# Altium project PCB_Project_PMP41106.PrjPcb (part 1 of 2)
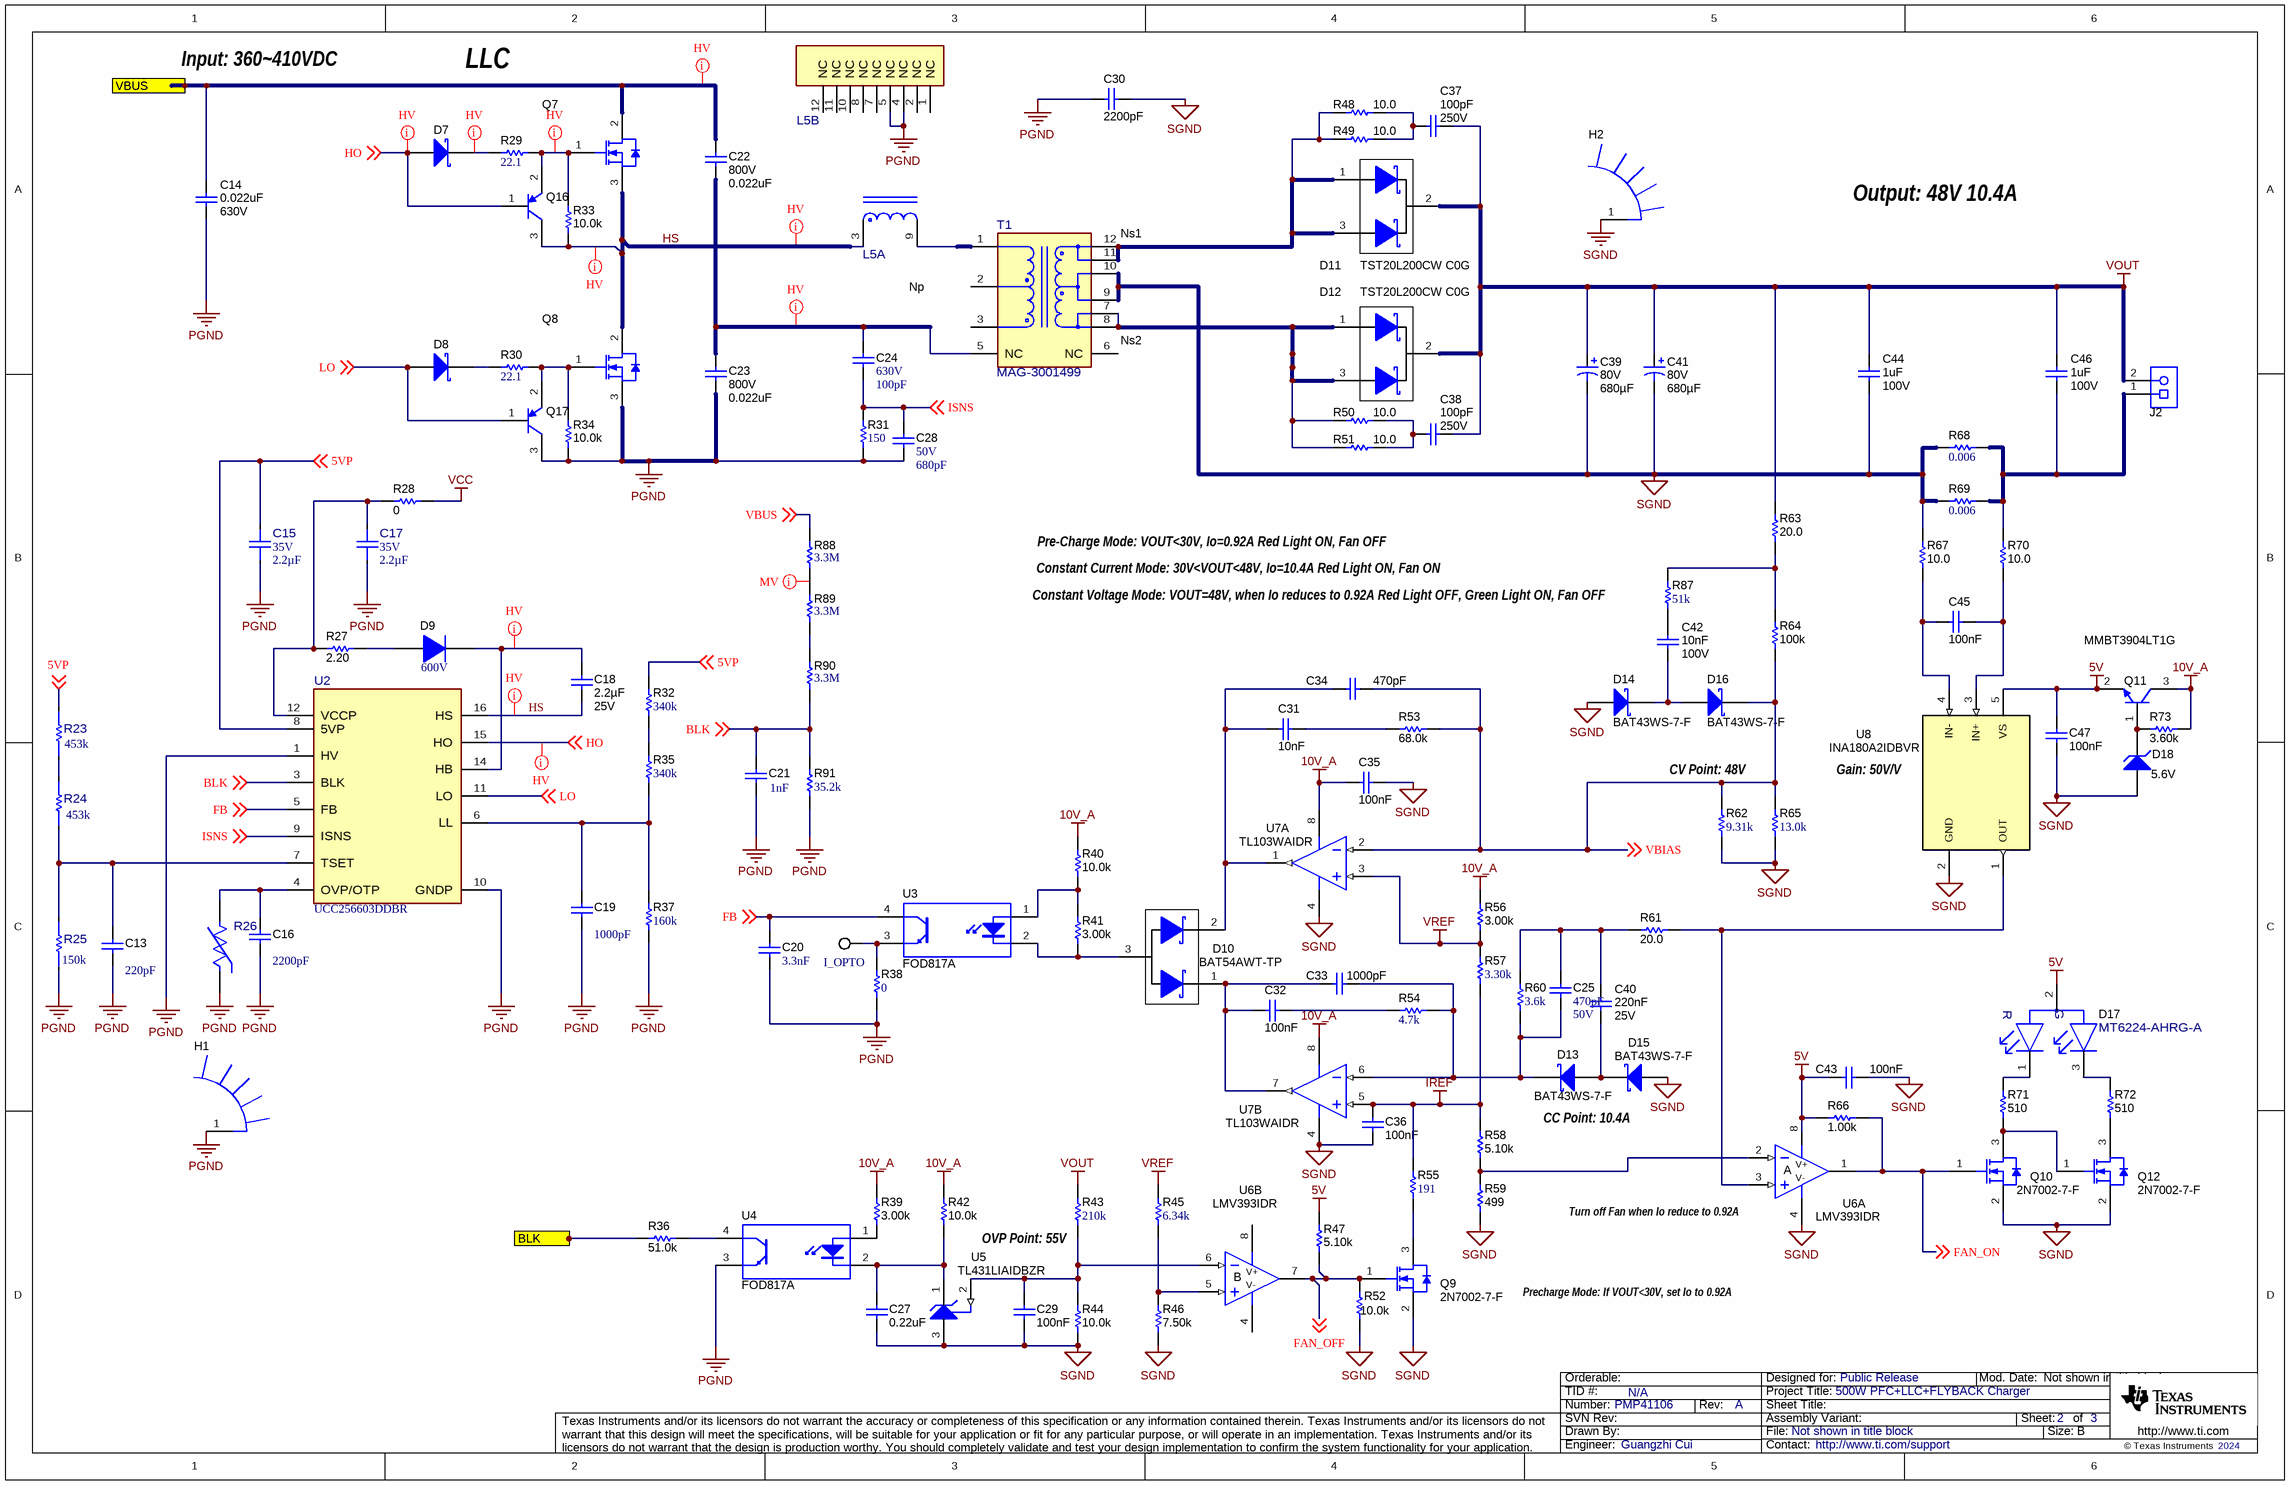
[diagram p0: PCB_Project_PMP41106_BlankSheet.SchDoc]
CopyrightYear: 2024; PCB_Layout: M Olinde; PCB_Rev: A; PRJ_Customer: Public Release; PRJ_Engineer: Guangzhi Cui; PRJ_Number: PMP41106; PRJ_Title: 500W PFC+LLC+FLYBACK Charger; SCH_Rev: A; TechSupport: http://www.ti.com/support; TID: N/A
3 sheets, 219 parts. Net scope: flat (ports and power ports of the same name join across sheets).
Board file: PCB_Project_PMP41106_PCB.PcbDoc
Sheets:
  PCB_Project_PMP41106_BlankSheet.SchDoc
  PCB_Project_PMP41106_CoverSheet.SchDoc
  PCB_Project_PMP41106_EVM_Hardware.SchDoc

## Sheet PCB_Project_PMP41106_BlankSheet.SchDoc
size 431 x 279 mm; Date: Not shown in title block; ApprovedBy: Not shown in title block; CheckedBy: Not shown in title block; Author: Not shown in title block; CompanyName: Not shown in title block; Engineer: Not shown in title block; Organization: Not shown in title block; Address1: Not shown in title block; Address2: Not shown in title block; Address3: Not shown in title block; Address4: Not shown in title block; DocumentNumber: 1; Revision: Use project parameter SCH_Rev; SheetNumber: 2; SheetTotal: 3; PageSetup: Record=PageOptions¦CenterHorizontal=True¦CenterVertical=True¦PrintScale=1.00¦XCorrection=1.00¦YCorrection=1.00¦PrintKind=0¦BorderSize=5000000¦LeftOffset=0¦BottomOffset=0¦Orientation=2¦PaperLength=1000¦PaperWidth=1000¦Scale=100¦PaperSource=15¦PrintQuality=600¦MediaType=1¦DitherType=10¦PaperKind=Letter¦PrintScaleMode=1

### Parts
C13  ValueDisplayed: 220pF  [0402L]  (hidden comment: C1005C0G1H221F050BA)
C14  VDC_V: 630V  ValueDisplayed: 0.022uF  [ECWF_L_1250x620x1050]  (hidden comment: ECW-F6223HL)
C15  VDC_V: 35V  Cap_F: 2.2µF  [FP-CGA4J1X7R1V225K125AC_0805-MFG]  (hidden comment: CGA4J1X7R1V225K125AC)
C16  ValueDisplayed: 2200pF  [0402L]  (hidden comment: GRM155R61E222KA01D)
C17  VDC_V: 35V  Cap_F: 2.2µF  [FP-CGA4J1X7R1V225K125AC_0805-MFG]  (hidden comment: CGA4J1X7R1V225K125AC)
C18  Cap_F: 2.2µF  VDC_V: 25V  [0805_150]  (hidden comment: 08053C225KAT2A)
C19  ValueDisplayed: 1000pF  [0402L]  (hidden comment: GRM155R72A102KA01D)
C20  Cap_F: 3.3nF  [0603]  (hidden comment: C0603C332K5RACTU)
C21  Cap_F: 1nF  [0402L]  (hidden comment: 04025C102JAT2A)
C22  VDC_V: 800V  ValueDisplayed: 0.022uF  [WCAP-FTX2_1500x700x1250]  (hidden comment: ECW-H8223HA)
C23  VDC_V: 800V  ValueDisplayed: 0.022uF  [WCAP-FTX2_1500x700x1250]  (hidden comment: ECW-H8223HA)
C24  VDC_V: 630V  ValueDisplayed: 100pF  [1206]  (hidden comment: GRM31A5C2J151JW01D)
C25  Cap_F: 470pF  VDC_V: 50V  [0603]  (hidden comment: 885012206081)
C27  ValueDisplayed: 0.22uF  [0603]  (hidden comment: GRM188R71E224KA88D)
C28  VDC_V: 50V  ValueDisplayed: 680pF  [0603]  (hidden comment: GRM1885C1H101JA01D)
C29  Cap_F: 100nF  [0603]  (hidden comment: C0603X104K3RACTU)
C30  ValueDisplayed: 2200pF  [C900_9x13]  (hidden comment: C921U222MVVDBA7317)
C31  Cap_F: 10nF  [0603]  (hidden comment: C0603X103K5RACTU)
C32  Cap_F: 100nF  [0603]  (hidden comment: C0603X104K3RACTU)
C33  ValueDisplayed: 1000pF  [0603]  (hidden comment: C0603C102K3GACTU)
C34  Cap_F: 470pF  [0603]  (hidden comment: C0603X471K5RACTU)
C35  Cap_F: 100nF  [0603]  (hidden comment: C0603X104K3RACTU)
C36  Cap_F: 100nF  [0603]  (hidden comment: C0603X104K3RACTU)
C37  VDC_V: 250V  ValueDisplayed: 100pF  [0805_HV]  (hidden comment: CL21C101JECNNWC)
C38  VDC_V: 250V  ValueDisplayed: 100pF  [0805_HV]  (hidden comment: CL21C101JECNNWC)
C39  VDC_V: 80V  ValueDisplayed: 680µF  [UES_1600x2500]  (hidden comment: EEUFS1K681)
C40  Cap_F: 220nF  VDC_V: 25V  [0603]  (hidden comment: C1608X7R1E224K080AC)
C41  VDC_V: 80V  ValueDisplayed: 680µF  [UES_1600x2500]  (hidden comment: EEUFS1K681)
C42  Cap_F: 10nF  VDC_V: 100V  [0603]  (hidden comment: C0603X103K1RACTU)
C43  Cap_F: 100nF  [0603]  (hidden comment: C0603X104K3RACTU)
C44  VDC_V: 100V  ValueDisplayed: 1uF  [1206_180]  (hidden comment: GRM31CR72A105KA01L)
C45  Cap_F: 100nF  [0603]  (hidden comment: C0603X104K3RACTU)
C46  VDC_V: 100V  ValueDisplayed: 1uF  [1206_180]  (hidden comment: GRM31CR72A105KA01L)
C47  Cap_F: 100nF  [0603]  (hidden comment: C0603X104K3RACTU)
D7  PMEG3010EGWJ  [SOD-123]  (value not drawn)
D8  PMEG3010EGWJ  [SOD-123]  (value not drawn)
D9  Vr_V: 600V  [SMAF]  (hidden comment: ES1JAF)
D10  BAT54AWT-TP  [SOT-323]
D11  TST20L200CW C0G  [TO-220AB]
D12  TST20L200CW C0G  [TO-220AB]
D13  BAT43WS-7-F  [SOD-323]
D14  BAT43WS-7-F  [SOD-323]
D15  BAT43WS-7-F  [SOD-323]
D16  BAT43WS-7-F  [SOD-323]
D17  MT6224-AHRG-A  [FP-MT6224-AHRG-A_RADIAL-MFG]
D18  value 5.6V  [SOD-323]  (hidden comment: MM3Z5V6ST1G)
H1  40mm*120mm  [Heatsink1]  (value not drawn)
H2  (no value)  [Heatsink2]
I_OPTO  5012  [Keystone5012]  (value not drawn)
J2  691216510002S  [Wurth_691216510002]  (value not drawn)
L5  MAG-3001500  [FP-MAG-3001500_PTH12-MFG]  (value not drawn)  (parts A,B of 2)
Q7  IPA60R170CFD7XKSA1  [TO-220_FullPAK_Offset]  (value not drawn)
Q8  IPA60R170CFD7XKSA1  [TO-220_FullPAK_Offset]  (value not drawn)
Q9  2N7002-7-F  [SOT-23]
Q10  2N7002-7-F  [SOT-23]
Q11  MMBT3904LT1G  [SOT-23]
Q12  2N7002-7-F  [SOT-23]
Q16  BC858C-7-F  [SOT-23]  (value not drawn)
Q17  BC858C-7-F  [SOT-23]  (value not drawn)
R23  value 453k  [0603]  (hidden comment: RC0603JR-070RL)
R24  value 453k  [0603]  (hidden comment: RC0603FR-0751K1L)
R25  value 150k  [0603]  (hidden comment: RC0603FR-07357KL)
R26  B57371V2474J060  [FP-B57371V2474J060_0603-MFG]  (value not drawn)
R27  ValueDisplayed: 2.20  [0603L]  (hidden comment: ERJ-3RQF2R2V)
R28  ValueDisplayed: 0  [1206]  (hidden comment: RC1206JR-070RL)
R29  ValueDisplayed: 22.1  [0603]  (hidden comment: RC0603FR-0722R1L)
R30  ValueDisplayed: 22.1  [0603]  (hidden comment: RC0603FR-0722R1L)
R31  ValueDisplayed: 150  [1206]  (hidden comment: RC1206FR-07221RL)
R32  ValueDisplayed: 340k  [FP-MCT0603MD1004BP500_0603-MFG]  (hidden comment: MCT0603MD1004BP500)
R33  ValueDisplayed: 10.0k  [0603]  (hidden comment: RC0603FR-0710KL)
R34  ValueDisplayed: 10.0k  [0603]  (hidden comment: RC0603FR-0710KL)
R35  ValueDisplayed: 340k  [FP-MCT0603MD1004BP500_0603-MFG]  (hidden comment: MCT0603MD1004BP500)
R36  ValueDisplayed: 51.0k  [0603]  (hidden comment: RC0603FR-0751KL)
R37  ValueDisplayed: 160k  [FP-RC0603JR-07130KL_0603-MFG]  (hidden comment: RC0603JR-07130KL)
R38  ValueDisplayed: 0  [0603]  (hidden comment: RCG060310K0FKEA)
R39  ValueDisplayed: 3.00k  [0603]  (hidden comment: RC0603FR-073KL)
R40  ValueDisplayed: 10.0k  [0603]  (hidden comment: RC0603FR-076K04L)
R41  ValueDisplayed: 3.00k  [0603]  (hidden comment: RC0603FR-073KL)
R42  ValueDisplayed: 10.0k  [0603]  (hidden comment: RC0603FR-0710KL)
R43  ValueDisplayed: 210k  [0603]  (hidden comment: RC0603FR-07301KL)
R44  ValueDisplayed: 10.0k  [0603]  (hidden comment: RC0603FR-0710KL)
R45  ValueDisplayed: 6.34k  [0603]  (hidden comment: RC0603FR-075K1L)
R46  ValueDisplayed: 7.50k  [0603]  (hidden comment: RC0603FR-077K5L)
R47  ValueDisplayed: 5.10k  [0603]  (hidden comment: RC0603FR-075K1L)
R48  ValueDisplayed: 10.0  [1206]  (hidden comment: RC1206FR-0710RL)
R49  ValueDisplayed: 10.0  [1206]  (hidden comment: RC1206FR-0710RL)
R50  ValueDisplayed: 10.0  [1206]  (hidden comment: RC1206FR-0710RL)
R51  ValueDisplayed: 10.0  [1206]  (hidden comment: RC1206FR-0710RL)
R52  ValueDisplayed: 10.0k  [0603]  (hidden comment: RC0603FR-0710KL)
R53  ValueDisplayed: 68.0k  [0603]  (hidden comment: RC0603FR-0768KL)
R54  ValueDisplayed: 4.7k  [0603]  (hidden comment: RC0603FR-072K4L)
R55  ValueDisplayed: 191  [0603]  (hidden comment: RC0603FR-07187RL)
R56  ValueDisplayed: 3.00k  [0603]  (hidden comment: RC0603FR-073KL)
R57  ValueDisplayed: 3.30k  [0603]  (hidden comment: RC0603FR-072K4L)
R58  ValueDisplayed: 5.10k  [0603]  (hidden comment: RC0603FR-075K1L)
R59  ValueDisplayed: 499  [0603]  (hidden comment: RC0603FR-07499RL)
R60  ValueDisplayed: 3.6k  [0603]  (hidden comment: RC0603FR-072KL)
R61  ValueDisplayed: 20.0  [0603]  (hidden comment: RC0603FR-0720RL)
R62  ValueDisplayed: 9.31k  [0603]  (hidden comment: CRCW060312K4FKEA)
R63  ValueDisplayed: 20.0  [0603]  (hidden comment: RC0603FR-0720RL)
R64  ValueDisplayed: 100k  [0603]  (hidden comment: RC0603FR-07100KL)
R65  ValueDisplayed: 13.0k  [0603]  (hidden comment: RC0603FR-075K11L)
R66  ValueDisplayed: 1.00k  [0603]  (hidden comment: RC0603FR-071KL)
R67  ValueDisplayed: 10.0  [0603]  (hidden comment: RC0603FR-0710RL)
R68  ValueDisplayed: 0.006  [1206]  (hidden comment: CSR1206FK10L0)
R69  ValueDisplayed: 0.006  [1206]  (hidden comment: CSR1206FK10L0)
R70  ValueDisplayed: 10.0  [0603]  (hidden comment: RC0603FR-0710RL)
R71  ValueDisplayed: 510  [0603]  (hidden comment: RC0603FR-07510RL)
R72  ValueDisplayed: 510  [0603]  (hidden comment: RC0603FR-07510RL)
R73  ValueDisplayed: 3.60k  [0603]  (hidden comment: RC0603FR-073K6L)
R87  ValueDisplayed: 51k  [0603]  (hidden comment: RC0603FR-07150KL)
R88  Res_ohm: 3.3M  [FP-KTR18EZPF3304_1206-MFG]  (hidden comment: KTR18EZPF3304)
R89  Res_ohm: 3.3M  [FP-KTR18EZPF3304_1206-MFG]  (hidden comment: KTR18EZPF3304)
R90  Res_ohm: 3.3M  [FP-KTR18EZPF3304_1206-MFG]  (hidden comment: KTR18EZPF3304)
R91  ValueDisplayed: 35.2k  [FP-ERA-3AEB3652V_0603-MFG]  (hidden comment: ERA-3AEB3652V)
T1  MAG-3001499  [FP-MAG-3001499_PTH_XFRMR_36MM0_35MM0-MFG]
U2  UCC256603DDBR  [DDB0014A-MFG]
U3  FOD817A  [DIP-4]
U4  FOD817A  [DIP-4]
U5  TL431LIAIDBZR  [DBZ0003A_N]
U6  LMV393IDR  [D0008A_L]  (parts A,B of 2)
U7  TL103WAIDR  [D0008A_L]  (parts A,B of 2)
U8  INA180A2IDBVR  [DBV0005A_N]

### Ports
BLK (in), VBUS (in)

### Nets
5V: C43.1 C47.1 D17.2(COMMON_ANODE) Q11.2(E) R47.2 R66.1 U6.8(V+) U8.5(VS)
10V_A: C35.1 Q11.3(C) R39.2 R40.2 R42.2 R56.1 R73.1 U7.8(VCC+)
IREF: C36.2 R55.2 R57.1 R58.2 U7.5(IN2+)
PGND: C13.2 C14.2 C15.1 C16.2 C17.1 C19.2 C20.2 C21.2 C23.2 C28.2 C30.2 H1.1 L5.4(NC) L5.5(NC) Q8.3(S) Q17.3(C) R25.1 R26.1 R31.1 R34.1 R37.1 R38.1 R91.1 U2.1(HV) U2.10(GNDP) U4.3(E)
SGND: C27.2 C29.2 C30.1 C35.2 C36.1 C39.2(-) C41.2(-) C43.2 C44.2 C47.2 D14.2(A) D15.2(A) D18.2(A) H2.1 Q9.2(S) Q10.2(S) Q12.2(S) R44.1 R46.1 R52.1 R59.1 R62.1 R65.1 R67.2 R68.1 R69.1 T1.9 T1.10 U5.3(ANODE) U6.4(V-) U7.4(VCC-) U8.2(GND)
VCC: R28.2
VOUT: C37.1 C38.1 C39.1(+) C41.1(+) C44.1 C46.1 D11.2(K) D12.2(K) J2.2 R43.2 R63.2
VREF: R45.2 R56.2 R57.2 U7.3(IN1+)
5VP: C15.2 R23.2 R32.2 U2.8(5VP) ; off-sheet 5VP
BLK: R36.2 ; port BLK
BLK: C21.1 R90.1 R91.2 U2.3(BLK) ; off-sheet BLK  [a separate net that carries the same name]
FAN_OFF: Q9.1(G) R47.1 R52.2 U6.7(OUT) ; off-sheet FAN_OFF
FAN_ON: Q10.1(G) R66.2 U6.1(OUT) ; off-sheet FAN_ON
FB: C20.1 U2.5(FB) U3.4(C) ; off-sheet FB
HO: D7.2(A) Q16.1(B) U2.15(HO) ; off-sheet HO
HS: C18.1 L5.3 Q7.3(S) Q8.2(D) Q16.3(C) R33.1 U2.16(HS)
ISNS: C24.2 C28.1 R31.2 U2.9(ISNS) ; off-sheet ISNS
LO: D8.2(A) Q17.1(B) U2.11(LO) ; off-sheet LO
VBIAS: C34.1 D16.1(K) R53.1 R62.2 R64.1 R65.2 U7.2(IN1-) ; off-sheet VBIAS
VBUS: C14.1 C22.1 Q7.2(D) ; port VBUS
VBUS: R88.2 ; off-sheet VBUS  [a separate net that carries the same name]
NetC13_1: C13.1 R24.1 R25.2 U2.7(TSET)
NetC16_1: C16.1 R26.2 U2.4(OVP/OTP)
NetC17_2: C17.2 R27.1 R28.1 U2.12(VCCP)
NetC18_2: C18.2 D9.1(K) U2.14(HB)
NetC19_1: C19.1 R35.1 R37.2 U2.6(LL)
NetC22_2: C22.2 C23.1 C24.1 T1.5(NC)
NetC25_1: C25.1 C40.1 R60.2 R61.2
NetC25_2: C25.2 C33.1 D13.1(K) R54.2 R60.1 U7.6(IN2-)
NetC27_1: C27.1 R42.1 U4.2(K) U5.1(CATHODE)
NetC29_1: C29.1 R43.1 R44.2 U5.2(REF) U6.6(IN-)
NetC31_1: C31.1 C34.2 D10.2(K) U7.1(OUT1)
NetC31_2: C31.2 R53.2
NetC32_1: C32.1 C33.2 D10.1(A) U7.7(OUT2)
NetC32_2: C32.2 R54.1
NetC37_2: C37.2 R48.2 R49.2
NetC38_2: C38.2 R50.2 R51.2
NetC40_2: C40.2 D13.2(A) D15.1(K)
NetC42_1: C42.1 R87.1
NetC42_2: C42.2 D14.1(K) D16.2(A)
NetC45_1: C45.1 R67.1 U8.4(IN-)
NetC45_2: C45.2 R70.1 U8.3(IN+)
NetC46_2: C46.2 J2.1 R68.2 R69.2 R70.2
NetD7_1: D7.1(K) R29.1
NetD8_1: D8.1(K) R30.1
NetD9_2: D9.2(A) R27.2
NetD10_3: D10.3(A) R41.2 U3.2(K)
NetD11_1: D11.1(A) D11.3(A) R48.1 R49.1 T1.11 T1.12
NetD12_1: D12.1(A) D12.3(A) R50.1 R51.1 T1.7 T1.8
NetD17_1: D17.1(RED_CATHODE) R71.2
NetD17_3: D17.3(GREEN_CATHODE) R72.2
NetD18_1: D18.1(K) Q11.1(B) R73.2
NetI_OPTO_1: I_OPTO.1 R38.2 U3.3(E)
NetL5_9: L5.9 T1.1
NetQ7_1: Q7.1(G) Q16.2(E) R29.2 R33.2
NetQ8_1: Q8.1(G) Q17.2(E) R30.2 R34.2
NetQ9_3: Q9.3(D) R55.1
NetQ10_3: Q10.3(D) Q12.1(G) R71.1
NetQ12_3: Q12.3(D) R72.1
NetR23_1: R23.1 R24.2
NetR32_1: R32.1 R35.2
NetR36_1: R36.1 U4.4(C)
NetR39_1: R39.1 U4.1(A)
NetR40_1: R40.1 R41.1 U3.1(A)
NetR45_1: R45.1 R46.2 U6.5(IN+)
NetR58_1: R58.1 R59.2 U6.2(IN-)
NetR61_1: R61.1 U6.3(IN+) U8.1(OUT)
NetR63_1: R63.1 R64.2 R87.2
NetR88_1: R88.1 R89.2
NetR89_1: R89.1 R90.2

Not connected (* = marked no-connect by the designer): L5 1(NC) 2(NC) 7(NC) 8(NC) 10(NC) 11(NC) 12(NC); T1 2 3 6(NC)

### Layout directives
net class HV: HO, HS, NetC18_2, NetC22_2, NetD7_1, NetQ7_1, VBUS
net class MV: NetR88_1

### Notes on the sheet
- Input: 360~410VDC
- LLC
- (near T1) Ns1
- Output: 48V 10.4A
- Np
- (near T1) Ns2
- Pre-Charge Mode: VOUT<30V, Io=0.92A Red Light ON, Fan OFF
- Constant Current Mode: 30V<VOUT<48V, Io=10.4A Red Light ON, Fan ON
- (near R87) Constant Voltage Mode: VOUT=48V, when Io reduces to 0.92A Red Light OFF, Green Light ON, Fan OFF
- CV Point: 48V
- Gain: 50V/V
- CC Point: 10.4A
- (near R43) OVP Point: 55V
- (near U6) Turn off Fan when Io reduce to 0.92A
- Precharge Mode: If VOUT<30V, set Io to 0.92A

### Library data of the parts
C13 = CMP-0006249-2: CAP, CERM, 220 pF, 50 V, +/- 1%, C0G/NP0, 0402; Manufacturer: TDK; TaMin_C: -55°C; Polarized: N; SizeAreaWB_mm2: 3; Value1: Unknown; U/M: EA; Value: 220pF; TaMax_C: 125°C; SizeZ_mm: 0.6; SizeX_mm: 1; SizeY_mm: 0.5; Cap_Case: 0402; Value2: 50V; AEC Category: Q200
C14 = CMP-0012506-3: CAP, Film, 0.022 uF, 630 V, +/- 3%, TH; Manufacturer: Panasonic; TaMin_C: -40°C; Polarized: N; Value1: Unknown; TaMax_C: 105°C; Cap_Case: 12.5x6.2x10.5mm; Cap_F: 22nF; AEC Category: Q200
C15 C17 = CMP-0089823-1: 2.2µF ±10% 35V Ceramic Capacitor X7R 0805 (2012 Metric); Manufacturer: TDK; TempCo: 15%; SizeZ_mm: 1.45mm; AEC Grade: Grade 1; AEC Qualified: Yes; ValueDisplayed: 2.2uF
C16 = CMP-0006609-2: CAP, CERM, 2200 pF, 25 V, +/- 10%, X5R, 0402; Manufacturer: MuRata; TaMin_C: -55°C; Polarized: N; SizeAreaWB_mm2: 3; Value1: Unknown; U/M: EA; Value: 2200pF; TaMax_C: 85°C; SizeZ_mm: 0.6; SizeX_mm: 1; SizeY_mm: 0.5; Cap_Case: 0402; Value2: 25V; Cap_F: 2.2nF; AEC Category: Q200
C18 = CMP-0007573-2: CAP, CERM, 2.2 uF, 25 V, +/- 10%, X7R, 0805; Manufacturer: AVX; TaMin_C: -55°C; Polarized: N; SizeAreaWB_mm2: 6.75; Value1: Unknown; U/M: EA; Value: 2.2uF; TaMax_C: 125°C; SizeZ_mm: 1.5; SizeX_mm: 2; SizeY_mm: 1.25; Cap_Case: 0805; SizeArea_mm2: 2.5; CompType: Capacitor; AEC Category: Q200
C19 = CMP-0006699-2: CAP, CERM, 1000 pF, 100 V, +/- 10%, X7R, 0402; Manufacturer: MuRata; TaMin_C: -55°C; Polarized: N; SizeAreaWB_mm2: 3; Value1: Unknown; U/M: EA; Value: 1000pF; TaMax_C: 125°C; SizeZ_mm: 0.6; SizeX_mm: 1; SizeY_mm: 0.5; Cap_Case: 0402; Value2: 100V; Cap_F: 1nF; AEC Category: Q200
C20 = CMP-0006922-4: CAP, CERM, 3300 pF, 50 V, +/- 10%, X7R, 0603; Manufacturer: Kemet; TaMin_C: -55°C; Polarized: N; SizeAreaWB_mm2: 4.68; Value1: Unknown; U/M: EA; Value: 3300pF; TaMax_C: 125°C; SizeZ_mm: 1; SizeX_mm: 1.6; SizeY_mm: 0.8; Value2: 50V; SizeArea_mm2: 1.28; AEC Category: Q200
C21 = CMP-0861060-1: CAP, CERM, 1000 pF, 50 V,+/- 5%, X7R, 0402; Manufacturer: AVX; Value2: 50V; SizeY_mm: 0.5; AEC Category: Q200; Polarized: N; Green_Lifecycle: Active; SizeAreaWB_mm2: 3; ValueDisplayed: 1000pF; Cap_Case: 0402; Value: 1000pF; TaMin_C: -55°C; U/M: EA; Green_REACh: Passed; SizeZ_mm: 0.6; SizeX_mm: 1; TaMax_C: 125°C
C22 C23 = CMP-0012312-3: CAP, Film, 0.022 uF, 800 V, +/- 3%, TH; Manufacturer: Panasonic Electronic Components; TaMin_C: -40°C; Polarized: N; SizeAreaWB_mm2: 153; Value1: Unknown; TaMax_C: 105°C; Tolerance_%: 10%; SizeZ_mm: 13; SizeX_mm: 15; SizeY_mm: 7; Cap_Case: 15x7x12.5; SizeArea_mm2: 105; CompType: Capacitor; Cap_F: 220nF; AEC Category: Q200
C24 = CMP-0008884-2: CAP, CERM, 100 pF, 630 V, +/- 5%, C0G/NP0, 1206; Manufacturer: MuRata; PartNumber: GRM31A5C2J101JW01D; TaMin_C: -55°C; Polarized: N; SizeAreaWB_mm2: 10.92; Value1: Unknown; U/M: EA; Value: 100pF; TaMax_C: 125°C; SizeZ_mm: 1.35; SizeX_mm: 3.2; SizeY_mm: 1.6; SizeArea_mm2: 5.12; AEC Category: Q200
C25 = CMP-0006834-5: CAP, CERM, 470 pF, 50 V, +/- 10%, X7R, 0603; Manufacturer: Wurth Elektronik; TaMin_C: -55°C; Polarized: N; SizeAreaWB_mm2: 4.68; Value1: Unknown; U/M: EA; Value: 470pF; TaMax_C: 125°C; SizeZ_mm: 1; SizeX_mm: 1.6; SizeY_mm: 0.8; SizeArea_mm2: 1.28; AEC Category: Q200
C27 = CMP-0007415-4: CAP, CERM, 0.22 uF, 25 V, +/- 10%, X7R, 0603; Manufacturer: MuRata; TaMin_C: -55°C; Polarized: N; SizeAreaWB_mm2: 4.68; Value1: Unknown; U/M: EA; Value: 0.22uF; TaMax_C: 125°C; SizeZ_mm: 1; SizeX_mm: 1.6; SizeY_mm: 0.8; Value2: 25V; SizeArea_mm2: 1.28; CompType: Capacitor; Cap_F: 220nF; AEC Category: Q200
C28 = CMP-0006959-4: CAP, CERM, 680 pF, 50 V, +/- 5%, C0G/NP0, 0603; Manufacturer: Kemet; PartNumber: C0603C681J5GACTU; TaMin_C: -55°C; Polarized: N; SizeAreaWB_mm2: 4.68; Value1: Unknown; U/M: EA; Value: 680pF; TaMax_C: 125°C; SizeZ_mm: 1; SizeX_mm: 1.6; SizeY_mm: 0.8; SizeArea_mm2: 1.28; AEC Category: Q200
C29 C32 C35 C36 C43 C45 C47 = CMP-0006979-5: CAP, CERM, 0.1 uF, 25 V, +/- 10%, X7R, 0603; Manufacturer: Kemet; TaMin_C: -55°C; Polarized: N; SizeAreaWB_mm2: 4.68; Value1: Unknown; U/M: EA; Value: 0.1uF; TaMax_C: 125°C; SizeZ_mm: 1; SizeX_mm: 1.6; SizeY_mm: 0.8; Value2: 25V; SizeArea_mm2: 1.28; CompType: Capacitor; AEC Category: Q200
C30 = CMP-0078358-1: CAP, CERM, 2200 pF, X1 400 VAC/Y1 400 VAC, +/- 20%, Y5V, D9xL13mm; Manufacturer: Kemet; Cap_F: 2.2nF; SizeAreaWB_mm2: 121; VAC_X: 400V; SizeArea_mm2: 81; AEC Qualified: N; AEC Category: Q200; Value: 2200pF; TaMax_C: 125°C; SizeZ_mm: 13; TaMin_C: -40°C; SizeY_mm: 9; U/M: EA; AC_Safety: X1Y1; Cap_Case: 9x13mm
C31 = CMP-0006978-4: CAP, CERM, 0.01 uF, 50 V, +/- 10%, X7R, 0603; Manufacturer: Kemet; TaMin_C: -55°C; Polarized: N; SizeAreaWB_mm2: 4.68; Value1: Unknown; U/M: EA; Value: 0.01uF; TaMax_C: 125°C; SizeZ_mm: 1; SizeX_mm: 1.6; SizeY_mm: 0.8; Value2: 50V; SizeArea_mm2: 1.28; CompType: Capacitor; AEC Category: Q200
C33 = CMP-0006846-4: CAP, CERM, 1000 pF, 25 V, +/- 10%, C0G/NP0, 0603; Manufacturer: Kemet; TaMin_C: -55°C; ESR_ohm: 0; Polarized: N; SizeAreaWB_mm2: 4.68; Value1: 0 ohm; U/M: EA; Value: 1000pF; TaMax_C: 125°C; SizeZ_mm: 1; SizeX_mm: 1.6; SizeY_mm: 0.8; Value2: 25V; SizeArea_mm2: 1.28; CompType: Capacitor; Cap_F: 1nF; IRMS_A: 0A; AEC Category: Q200
C34 = CMP-0006986-4: CAP, CERM, 470 pF, 50 V, +/- 10%, X7R, 0603; Manufacturer: Kemet; TaMin_C: -55°C; SizeAreaWB_mm2: 4.68; Value1: Unknown; U/M: EA; Value: 470pF; TaMax_C: 125°C; SizeZ_mm: 1; SizeX_mm: 1.6; SizeY_mm: 0.8; Value2: 50V; SizeArea_mm2: 1.28; CompType: Capacitor; AEC Category: Q200; Polarized: N
C37 C38 = CMP-0074690-1: CAP, CERM, 100 pF, 250 V,+/- 5%, C0G/NP0, 0805; Manufacturer: Samsung Electro-Mechanics; TaMin_C: -55°C; Polarized: N; SizeAreaWB_mm2: 6.75; U/M: EA; Value: 100pF; TaMax_C: 125°C; SizeZ_mm: 1.45; SizeX_mm: 2.0; SizeY_mm: 1.25; Cap_Case: 0805; SizeArea_mm2: 2.5; AEC Category: Q200
C39 C41 = CMP-0077674-1: CAP, AL, 680 µF, 80 V, +/- 20%, TH; Manufacturer: Panasonic Electronic Components; SizeAreaWB_mm2: 324.0; SizeArea_mm2: 256.0; AEC Qualified: N; AEC Category: Q200; Value: 680uF; TaMax_C: 105°C; SizeZ_mm: 26.5; Polarized: Y; TaMin_C: -40°C; SizeY_mm: 16.0; U/M: EA; CompType: Capacitor; Cap_Case: 16x25mm
C40 = CMP-0007042-4: CAP, CERM, 0.22 uF, 25 V, +/- 10%, X7R, 0603; Manufacturer: TDK; TaMin_C: -55°C; Polarized: N; SizeAreaWB_mm2: 4.68; Value1: Unknown; U/M: EA; Value: 0.22uF; TaMax_C: 125°C; SizeZ_mm: 1; SizeX_mm: 1.6; SizeY_mm: 0.8; SizeArea_mm2: 1.28; AEC Category: Q200
C42 = CMP-0006977-4: CAP, CERM, 0.01 uF, 100 V, +/- 10%, X7R, 0603; Manufacturer: Kemet; TaMin_C: -55°C; Polarized: N; SizeAreaWB_mm2: 4.68; Value1: Unknown; U/M: EA; Value: 0.01uF; TaMax_C: 125°C; SizeZ_mm: 1; SizeX_mm: 1.6; SizeY_mm: 0.8; SizeArea_mm2: 1.28; AEC Category: Q200
C44 C46 = CMP-0008970-2: CAP, CERM, 1 uF, 100 V, +/- 10%, X7R, 1206; Manufacturer: MuRata; TaMin_C: -55°C; Polarized: N; SizeAreaWB_mm2: 10.92; Value1: Unknown; U/M: EA; Value: 1uF; TaMax_C: 125°C; SizeZ_mm: 1.8; SizeX_mm: 3.2; SizeY_mm: 1.6; Cap_Case: 2220; SizeArea_mm2: 5.12; Cap_F: 1µF; AEC Category: Q200
D7 D8 = CMP-0079240-2: Diode, Schottky, 30 V, 1 A, AEC-Q101, SOD-123; Manufacturer: Nexperia; SizeZ_mm: 1.35; Value: 30V; Value1: 1A; AEC Category: Q101; Vf_V: 560mV; SizeX_mm: 3.85; SizeAreaWB_mm2: 13.095; Value2: 0.56V; SizeY_mm: 1.7; AEC Qualified: Y; TJmax_C: 150°C; SizeArea_mm2: 6.545
D9 = CMP-0029162-2: Diode, Ultrafast, 600 V, 1 A, AEC-Q101, SMAF; Manufacturer: Fairchild Semiconductor; Io_A: 1A; Green_Lifecycle: Not Set; SizeAreaWB_mm2: 19.95; Green_REACh: Incomplete; TJmax_C: 150°C; Value: 600V; SizeZ_mm: 1; SizeX_mm: 4.7; SizeY_mm: 2.5; Vf_V: 1.7V; SizeArea_mm2: 11.75; AEC Qualified: Y; AEC Category: Q101
D10 = CMP-0028627-2: Diode, Schottky, 30 V, 0.2 A, SOT-323; Manufacturer: Micro Commercial Components; SizeArea_mm2: 4.84; Io_A: 2dA; Value2: 1V; Value1: 0.2A; TJmax_C: 125°C; SizeY_mm: 2.2; AEC Category: Q101; SizeZ_mm: 1.1; Green_REACh: Incomplete; Value: 30V; Green_Lifecycle: Not Set; SizeAreaWB_mm2: 10.24
D11 D12 = CMP-0028764-3: Diode, Schottky, 200 V, 20 A, TH; Manufacturer: Taiwan Semiconductor Corporation; RJC_CperW: 2; SizeArea_mm2: 45.9; Value1: 20A; Value2: 0.99V; Value: 200V; AEC Qualified: N; SizeY_mm: 4.5; AEC Category: Q101; SizeAreaWB_mm2: 79.3; Green_Lifecycle: Not Set; Green_REACh: Incomplete; Vf_V: 9.9dV; TJmax_C: 150°C; SizeX_mm: 10.2; SizeZ_mm: 19.4
D13-D16 = CMP-0028449-2: Diode, Schottky, 30 V, 0.2 A, SOD-323; Manufacturer: Diodes Inc.; SizeZ_mm: 1; Value1: 0.2A; SizeArea_mm2: 3.645; Io_A: 2dA; Value: 30V; SizeAreaWB_mm2: 8.695; SizeY_mm: 1.35; AEC Category: Q101; Vf_V: 1V; Green_REACh: Incomplete; SizeX_mm: 2.7; Green_Lifecycle: Not Set
D17 = CMP-0087778-1: LED GRN/RED DIFF 5MM ROUND T/H; Manufacturer: Marktech Optoelectronics; Color: Green, Red; LambdaP: 568/630nm; Angle: 70°; Vr_V: 5V; LambdaD: 570/622nm
D18 = CMP-0085741-1: Diode, Zener, 5.6 V, 300 mW, SOD-323; Manufacturer: ON Semiconductor; AEC Category: Q101; SizeZ_mm: 1; SizeArea_mm2: 3.645; AEC Qualified: N; Value1: 0.3W; Power_W: 300mW; SizeX_mm: 2.7; SizeAreaWB_mm2: 8.695; RJA_CperW: 416; SizeY_mm: 1.35
H1 = 7106DG: CompType: Heatsink
H2 = 7106DG: PartNumber: 40mm*40mm; CompType: Heatsink
I_OPTO = CMP-0055149-2: Test Point, Multipurpose, White, TH; Manufacturer: Keystone Electronics; CNHeader: FALSE; Green_Lifecycle: Active; Green_REACh: Passed; ContactFinish: Silver; CT: TRUE
J2 = CMP-0054770-2: Receptacle, 5.08mm, 2x1, Brass, TH; Manufacturer: Wurth Elektronik; Pitch_mm: 5.08; CNHeader: FALSE; Gender: Female; Row_Count: 1; Cert_UL: Y; Current_A: 10A; Voltage_V: 300V
L5 = CMP-0120782-1: LLC INDUCTOR; Manufacturer: Bourns; AEC Qualified: No; DCR_ohm: 50m; Ind_H: 58µH; SizeZ_mm: 21mm; Value: 58uH; Test Frequency: 100Hz; Tolerance_%: 10%
Q7 Q8 = CMP-0079306-2: MOSFET, N-CH, 600 V, 8 A, TO-220FP; Alternate Manufacturer: None; Manufacturer: Infineon Technologies; SizeArea_mm2: 45.9; Vgs_V: 20V; Value2: 28 nC; QgTyp_nC: 28; AEC Qualified: N; SizeX_mm: 10.2; Value: 600V; Value1: ? ohm; AEC Category: Q101; ChMode: Enhancement; SizeZ_mm: 20; IdsMax_A: 8A; SizeAreaWB_mm2: 79.3; SizeY_mm: 4.5
Q9 Q10 Q12 = CMP-0000769-1: MOSFET, N-CH, 60 V, 0.17 A, SOT-23; Alternate Manufacturer: None; Manufacturer: Diodes Inc.; SizeZ_mm: 1.1; ChType: N; Value2: 223 nC; Value1: 7; VdsMax_V: 60V; SizeX_mm: 2.5; SizeY_mm: 3; Vgs_V: 20V; Value: 60V; Rdson45_ohm: 7.5; AEC Category: Q101; IdsMax_A: 1.7dA; SizeAreaWB_mm2: 14; U/M: EA; QgTyp_nC: 223
Q11 = CMP-0000419-2: Transistor, NPN, 40 V, 0.2 A, SOT-23; Manufacturer: ON Semiconductor; TaMax_C: 150°C; Value2: 300; Value1: 0.2 A; Vcesat1_V: 3dV; SizeX_mm: 2.5; SizeY_mm: 3; TaMin_C: -55°C; IcRated_A: 2dA; CompType: BJT; SizeZ_mm: 1.1; Value: 40 V; SizeArea_mm2: 7.5; NPN: 1; Vceo_V: 40V; PNP: 0; AEC Category: Q101; SizeAreaWB_mm2: 14; U/M: EA
Q16 Q17 = CMP-0000317-2: Transistor, PNP, 30 V, 0.1 A, SOT-23; Manufacturer: Diodes Inc.; TaMax_C: 150°C; Value2: 600; Value1: 0.1 A; Vcesat1_V: 75mV; SizeX_mm: 2.5; SizeY_mm: 3; TaMin_C: -65°C; IcRated_A: 1dA; CompType: BJT; SizeZ_mm: 1.1; Value: 30 V; SizeArea_mm2: 7.5; NPN: 0; Vceo_V: 30V; PNP: 1; AEC Category: Q101; SizeAreaWB_mm2: 14; U/M: EA
R23 R24 = CMP-0093030-1: 453 kOhms ±0.1% 0.063W, 1/16W Chip Resistor 0603 (1608 Metric) Thin Film; Manufacturer: TE Connectivity; Part Number: RN73C1J453KBTD; Power_W: 63mW; VDC_V: 50V; TempCo: 10ppm/°C; SizeZ_mm: 0.55mm; AEC Qualified: No
R25 = CMP-0094963-1: 150kΩ ±1% 0.1W 0603 Thick Film Chip Resistor AEC-Q200 compliant; PartNumber: RMCF0603FT150K; Manufacturer: Stackpole Electronics; AEC Qualified: Yes; Power_W: 100mW; SizeZ_mm: 0.55mm; AEC Grade: Grade 0; VDC_V: 75V; TempCo: 100ppm/°C
R26 = CMP-0096703-1: NTC Thermistor 470k 0603 (1608 Metric); Manufacturer: TDK; AEC Qualified: No; Res_ohm: 470kΩ; Power_W: 180mW; B 25 50: 4386K; B 25 100: 4480K; SizeZ_mm: 0.9mm; B 25 85: 4455K; B Tolerance: 3%; Tolerance_%: 5%
R27 = CMP-0022711-2: RES, 2.20, 1%, 0.1 W, 0603; Manufacturer: Panasonic; Power_W: 100mW; TempCo: 200 ppm/C; Value_Code: 2R20; U/M: EA; Value: 2.20; Res_ohm: 2.2; SizeX_mm: 1.6; SizeY_mm: 0.8; SizeZ_mm: 1; Value2: 0.1W; SizeArea_mm2: 1.28; CompType: Resistor; AEC Category: Q200
R28 = CMP-0018759-2: RES, 0, 5%, 0.25 W, 1206; Manufacturer: Yageo America; Power_W: 250mW; TempCo: 200 ppm/C; Value_Code: 0000; U/M: EA; Value: 0; EIA_Code: E24; SizeX_mm: 3.2; SizeY_mm: 1.6; SizeZ_mm: 1.35; Value2: 0.25W; SizeArea_mm2: 5.12; VDC_V: 200V; AEC Category: Q200
R29 R30 = CMP-0022926-4: RES, 22.1, 1%, 0.1 W, 0603; Manufacturer: Yageo; Power_W: 100mW; TempCo: 100 ppm/C; Value_Code: 22R1; Value: 22.1; EIA_Code: E96; SizeX_mm: 1.6; SizeY_mm: 0.8; SizeZ_mm: 1; Value2: 0.1W; SizeArea_mm2: 1.28; AEC Qualified: N; VDC_V: 75V; AEC Category: Q200; SizeAreaWB_mm2: 4.68
R31 = CMP-0022809-5: RES, 150, 1%, 0.1 W, 0603; Manufacturer: Yageo; PartNumber: RC0603FR-07150RL; Power_W: 100mW; TempCo: 100 ppm/C; Value_Code: 150R; Value: 150; EIA_Code: E96; SizeX_mm: 1.6; SizeY_mm: 0.8; SizeZ_mm: 1; Value2: 0.1W; SizeArea_mm2: 1.28; AEC Qualified: N; VDC_V: 75V; AEC Category: Q200; SizeAreaWB_mm2: 4.68
R32 R35 = CMP-0022342-4: RES, 340 k, 1%, 0.1 W, AEC-Q200 Grade 0, 0603; Manufacturer: Vishay-Dale; PartNumber: CRCW0603340KFKEA; Power_W: 100mW; TempCo: 100 ppm/C; Value: 340k; EIA_Code: E96; SizeX_mm: 1.6; SizeY_mm: 0.8; SizeZ_mm: 1; Value2: 0.1W; SizeArea_mm2: 1.28; AEC Qualified: Y; VDC_V: 75V; AEC Category: Q200; AEC Grade: 0
R33 R34 R42 R44 R52 = CMP-0022746-5: RES, 10.0 k, 1%, 0.1 W, 0603; Manufacturer: Yageo; Power_W: 100mW; TempCo: 100 ppm/C; Value_Code: 10k0; Value: 10.0k; EIA_Code: E96; Res_ohm: 10k; SizeX_mm: 1.6; SizeY_mm: 0.8; SizeZ_mm: 1; Value2: 0.1W; SizeArea_mm2: 1.28; AEC Qualified: N; VDC_V: 75V; AEC Category: Q200; SizeAreaWB_mm2: 4.68
R36 = CMP-0023167-5: RES, 51.0 k, 1%, 0.1 W, 0603; Manufacturer: Yageo; Power_W: 100mW; TempCo: 100 ppm/C; Value_Code: 51k0; Value: 51.0k; Res_ohm: 51k; SizeX_mm: 1.6; SizeY_mm: 0.8; SizeZ_mm: 1; Value2: 0.1W; SizeArea_mm2: 1.28; AEC Qualified: N; VDC_V: 75V; AEC Category: Q200; SizeAreaWB_mm2: 4.68
R37 = CMP-0022072-4: RES, 160 k, 1%, 0.1 W, AEC-Q200 Grade 0, 0603; Manufacturer: Vishay-Dale; PartNumber: CRCW0603160KFKEA; Power_W: 100mW; TempCo: 100 ppm/C; Value: 160k; SizeX_mm: 1.6; SizeY_mm: 0.8; SizeZ_mm: 1; Value2: 0.1W; SizeArea_mm2: 1.28; AEC Qualified: Y; VDC_V: 75V; AEC Category: Q200; AEC Grade: 0
R38 = CMP-0025885-5: RES, 0, 5%, 0.1 W, 0603; Manufacturer: Yageo; PartNumber: RC0603JR-070RL; Power_W: 100mW; TempCo: 200 ppm/C; Value_Code: 0000; Value: 0; EIA_Code: E24; SizeX_mm: 1.6; SizeZ_mm: 1; Value2: 0.1W; SizeArea_mm2: 1.28; AEC Qualified: N; VDC_V: 75V; AEC Category: Q200; SizeY_mm: 0.8; SizeAreaWB_mm2: 4.68
R39 R41 R56 = CMP-0023091-5: RES, 3.00 k, 1%, 0.1 W, 0603; Manufacturer: Yageo; Power_W: 100mW; TempCo: 100 ppm/C; Value_Code: 3k00; Value: 3.00k; Res_ohm: 3k; SizeX_mm: 1.6; SizeY_mm: 0.8; SizeZ_mm: 1; Value2: 0.1W; SizeArea_mm2: 1.28; AEC Qualified: N; VDC_V: 75V; AEC Category: Q200; SizeAreaWB_mm2: 4.68
R40 = CMP-0022746-5: RES, 10.0 k, 1%, 0.1 W, 0603; Manufacturer: Yageo; PartNumber: RC0603FR-0710KL; Power_W: 100mW; TempCo: 100 ppm/C; Value_Code: 10k0; Value: 10.0k; EIA_Code: E96; Res_ohm: 10k; SizeX_mm: 1.6; SizeY_mm: 0.8; SizeZ_mm: 1; Value2: 0.1W; SizeArea_mm2: 1.28; AEC Qualified: N; VDC_V: 75V; AEC Category: Q200; SizeAreaWB_mm2: 4.68
R43 = CMP-0022909-4: RES, 210 k, 1%, 0.1 W, 0603; Manufacturer: Yageo; PartNumber: RC0603FR-07210KL; Power_W: 100mW; TempCo: 100 ppm/C; Value: 210k; EIA_Code: E96; SizeX_mm: 1.6; SizeY_mm: 0.8; SizeZ_mm: 1; Value2: 0.1W; SizeArea_mm2: 1.28; AEC Qualified: N; VDC_V: 75V; AEC Category: Q200; SizeAreaWB_mm2: 4.68
R45 = CMP-0023249-5: RES, 6.34 k, 1%, 0.1 W, 0603; PartNumber: RC0603FR-076K34L; Manufacturer: Yageo; EIA_Code: E96; SizeAreaWB_mm2: 4.68; Power_W: 100mW; TempCo: 100 ppm/C; Value_Code: 6k34; Value: 6.34k; SizeX_mm: 1.6; SizeY_mm: 0.8; SizeZ_mm: 1; Value2: 0.1W; SizeArea_mm2: 1.28; AEC Qualified: N; VDC_V: 75V; AEC Category: Q200
R46 = CMP-0023279-5: RES, 7.50 k, 1%, 0.1 W, 0603; Manufacturer: Yageo; Power_W: 100mW; TempCo: 100 ppm/C; Value_Code: 7k50; Value: 7.50k; EIA_Code: E96; Res_ohm: 7.5k; SizeX_mm: 1.6; SizeY_mm: 0.8; SizeZ_mm: 1; Value2: 0.1W; SizeArea_mm2: 1.28; AEC Qualified: N; VDC_V: 75V; AEC Category: Q200; SizeAreaWB_mm2: 4.68
R47 R58 = CMP-0023198-5: RES, 5.10 k, 1%, 0.1 W, 0603; Manufacturer: Yageo; Power_W: 100mW; TempCo: 100 ppm/C; Value_Code: 5k10; Value: 5.10k; Res_ohm: 5.1k; SizeX_mm: 1.6; SizeY_mm: 0.8; SizeZ_mm: 1; Value2: 0.1W; SizeArea_mm2: 1.28; AEC Qualified: N; VDC_V: 75V; AEC Category: Q200; SizeAreaWB_mm2: 4.68
R48-R51 = CMP-0017851-2: RES, 10.0, 1%, 0.25 W, 1206; Manufacturer: Yageo America; Power_W: 250mW; TempCo: 200 ppm/C; Value_Code: 10R0; U/M: EA; Value: 10.0; EIA_Code: E96; Res_ohm: 10; SizeX_mm: 3.2; SizeY_mm: 1.6; SizeZ_mm: 1.35; Value2: 0.25W; SizeArea_mm2: 5.12; VDC_V: 200V; AEC Category: Q200
R53 = CMP-0023239-5: RES, 68.0 k, 1%, 0.1 W, 0603; Manufacturer: Yageo; Power_W: 100mW; TempCo: 100 ppm/C; Value_Code: 68k0; Value: 68.0k; Res_ohm: 68k; SizeX_mm: 1.6; SizeY_mm: 0.8; SizeZ_mm: 1; Value2: 0.1W; SizeArea_mm2: 1.28; AEC Qualified: N; VDC_V: 75V; AEC Category: Q200; SizeAreaWB_mm2: 4.68
R54 = CMP-0025927-5: RES, 4.7 k, 5%, 0.1 W, 0603; Manufacturer: Yageo; PartNumber: RC0603JR-074K7L; Power_W: 100mW; TempCo: 100 ppm/C; Value_Code: 4k70; Value: 4.7k; EIA_Code: E24; SizeX_mm: 1.6; SizeY_mm: 0.8; SizeZ_mm: 1; Value2: 0.1W; SizeArea_mm2: 1.28; AEC Qualified: N; VDC_V: 75V; AEC Category: Q200; SizeAreaWB_mm2: 4.68
R55 = CMP-0022857-5: RES, 191, 1%, 0.1 W, 0603; Manufacturer: Yageo; PartNumber: RC0603FR-07191RL; Power_W: 100mW; TempCo: 100 ppm/C; Value_Code: 191R; Value: 191; EIA_Code: E96; SizeX_mm: 1.6; SizeY_mm: 0.8; SizeZ_mm: 1; Value2: 0.1W; SizeArea_mm2: 1.28; AEC Qualified: N; VDC_V: 75V; AEC Category: Q200; SizeAreaWB_mm2: 4.68
R57 = CMP-0023081-5: RES, 3.30 k, 1%, 0.1 W, 0603; PartNumber: RC0603FR-073K3L; Manufacturer: Yageo; Power_W: 100mW; TempCo: 100 ppm/C; Value_Code: 3k30; Value: 3.30k; Res_ohm: 3.3k; SizeX_mm: 1.6; SizeY_mm: 0.8; SizeZ_mm: 1; Value2: 0.1W; SizeArea_mm2: 1.28; AEC Qualified: N; VDC_V: 75V; AEC Category: Q200; SizeAreaWB_mm2: 4.68
R59 = CMP-0023141-5: RES, 499, 1%, 0.1 W, 0603; Manufacturer: Yageo; Power_W: 100mW; TempCo: 100 ppm/C; Value_Code: 499R; Value: 499; EIA_Code: E96; SizeX_mm: 1.6; SizeY_mm: 0.8; SizeZ_mm: 1; Value2: 0.1W; SizeArea_mm2: 1.28; AEC Qualified: N; VDC_V: 75V; AEC Category: Q200; SizeAreaWB_mm2: 4.68
R60 = CMP-0025919-5: RES, 3.6 k, 5%, 0.1 W, 0603; Manufacturer: Yageo; PartNumber: RC0603JR-073K6L; Power_W: 100mW; TempCo: 100 ppm/C; Value_Code: 3k60; Value: 3.6k; EIA_Code: E24; SizeX_mm: 1.6; SizeY_mm: 0.8; SizeZ_mm: 1; Value2: 0.1W; SizeArea_mm2: 1.28; AEC Qualified: N; VDC_V: 75V; AEC Category: Q200; SizeAreaWB_mm2: 4.68
R61 R63 = CMP-0022908-4: RES, 20.0, 1%, 0.1 W, 0603; Manufacturer: Yageo; Power_W: 100mW; TempCo: 100 ppm/C; Value_Code: 20R0; Value: 20.0; EIA_Code: E96; Res_ohm: 20; SizeX_mm: 1.6; SizeY_mm: 0.8; SizeZ_mm: 1; Value2: 0.1W; SizeArea_mm2: 1.28; AEC Qualified: N; VDC_V: 75V; AEC Category: Q200; SizeAreaWB_mm2: 4.68
R62 = CMP-0022666-4: RES, 9.31 k, 1%, 0.1 W, AEC-Q200 Grade 0, 0603; Manufacturer: Vishay-Dale; PartNumber: CRCW06039K31FKEA; Power_W: 100mW; TempCo: 100 ppm/C; Value_Code: 9k31; Value: 9.31k; EIA_Code: E96; SizeX_mm: 1.6; SizeY_mm: 0.8; SizeZ_mm: 1; Value2: 0.1W; SizeArea_mm2: 1.28; AEC Qualified: Y; VDC_V: 75V; AEC Category: Q200; AEC Grade: 0
R64 = CMP-0022735-5: RES, 100 k, 1%, 0.1 W, 0603; Manufacturer: Yageo; Power_W: 100mW; TempCo: 100 ppm/C; Value: 100k; EIA_Code: E96; SizeX_mm: 1.6; SizeY_mm: 0.8; SizeZ_mm: 1; Value2: 0.1W; SizeArea_mm2: 1.28; AEC Qualified: N; VDC_V: 75V; AEC Category: Q200; SizeAreaWB_mm2: 4.68
R65 = CMP-0022042-4: RES, 13.0 k, 1%, 0.1 W, AEC-Q200 Grade 0, 0603; Manufacturer: Vishay-Dale; PartNumber: CRCW060313K0FKEA; Power_W: 100mW; TempCo: 100 ppm/C; Value_Code: 13k0; Value: 13.0k; EIA_Code: E96; Res_ohm: 13k; SizeX_mm: 1.6; SizeY_mm: 0.8; SizeZ_mm: 1; Value2: 0.1W; SizeArea_mm2: 1.28; AEC Qualified: Y; VDC_V: 75V; AEC Category: Q200; AEC Grade: 0
R66 = CMP-0022895-5: RES, 1.00 k, 1%, 0.1 W, 0603; Manufacturer: Yageo; Power_W: 100mW; TempCo: 100 ppm/C; Value_Code: 1k00; Value: 1.00k; EIA_Code: E96; Res_ohm: 1k; SizeX_mm: 1.6; SizeY_mm: 0.8; SizeZ_mm: 1; Value2: 0.1W; SizeArea_mm2: 1.28; AEC Qualified: N; VDC_V: 75V; AEC Category: Q200; SizeAreaWB_mm2: 4.68
R67 R70 = CMP-0022751-4: RES, 10.0, 1%, 0.1 W, 0603; Manufacturer: Yageo; Power_W: 100mW; TempCo: 100 ppm/C; Value_Code: 10R0; Value: 10.0; EIA_Code: E96; Res_ohm: 10; SizeX_mm: 1.6; SizeY_mm: 0.8; SizeZ_mm: 1; Value2: 0.1W; SizeArea_mm2: 1.28; AEC Qualified: N; VDC_V: 75V; AEC Category: Q200; SizeAreaWB_mm2: 4.68
R68 R69 = CMP-0018567-2: RES, 0.006, 1%, 0.5 W, 1206; Manufacturer: Vishay-Dale; PartNumber: WSL12066L000FEA18; Power_W: 500mW; TempCo: 110 ppm/C; Value_Code: 6L000; U/M: EA; Value: 0.006; EIA_Code: E96; Res_ohm: 6m; SizeX_mm: 3.2; SizeY_mm: 1.6; SizeZ_mm: 1.35; Value2: 0.5W; SizeArea_mm2: 5.12; AEC Category: Q200
R71 R72 = CMP-0023163-5: RES, 510, 1%, 0.1 W, 0603; Manufacturer: Yageo; Power_W: 100mW; TempCo: 100 ppm/C; Value_Code: 510R; Value: 510; SizeX_mm: 1.6; SizeY_mm: 0.8; SizeZ_mm: 1; Value2: 0.1W; SizeArea_mm2: 1.28; AEC Qualified: N; VDC_V: 75V; AEC Category: Q200; SizeAreaWB_mm2: 4.68
R73 = CMP-0023086-5: RES, 3.60 k, 1%, 0.1 W, 0603; Manufacturer: Yageo; Power_W: 100mW; TempCo: 100 ppm/C; Value_Code: 3k60; Value: 3.60k; Res_ohm: 3.6k; SizeX_mm: 1.6; SizeY_mm: 0.8; SizeZ_mm: 1; Value2: 0.1W; SizeArea_mm2: 1.28; AEC Qualified: N; VDC_V: 75V; AEC Category: Q200; SizeAreaWB_mm2: 4.68
R87 = CMP-0025929-5: RES, 51 k, 5%, 0.1 W, 0603; Manufacturer: Yageo; PartNumber: RC0603JR-0751KL; Power_W: 100mW; TempCo: 100 ppm/C; Value_Code: 51k0; Value: 51k; EIA_Code: E24; SizeX_mm: 1.6; SizeY_mm: 0.8; SizeZ_mm: 1; Value2: 0.1W; SizeArea_mm2: 1.28; AEC Qualified: N; VDC_V: 75V; AEC Category: Q200; SizeAreaWB_mm2: 4.68
R88-R90 = CMP-0087456-2: 3.3 MOhms ±1% 0.25W, 1/4W Chip Resistor 1206 (3216 Metric) Automotive AEC-Q200, High Voltage Thick Film; Manufacturer: Rohm Semiconductor; AEC Qualified: Yes; Power_W: 250mW; SizeZ_mm: 0.65mm; AEC Grade: Grade 0; TempCo: 100ppm/°C; VDC_V: 500V
R91 = CMP-0024146-3: RES, 35.2 k, 0.1%, 0.1 W, 0603; Manufacturer: Yageo America; PartNumber: RT0603BRD0735K2L; Power_W: 100mW; TempCo: 25 ppm/C; Value_Code: 35k2; U/M: EA; Value: 35.2k; EIA_Code: E192; SizeX_mm: 1.6; SizeY_mm: 0.8; SizeZ_mm: 1; Value2: 0.1W; SizeArea_mm2: 1.28; VDC_V: 75V; AEC Category: Q200
T1 = CMP-0120781-1: LLC TRANSFORMER; Manufacturer: Bourns; Ind_H: 200µH; Ns1toNp: 10:10:6:6; SizeZ_mm: 34.2mm; AEC Qualified: No; Voltage_Isolation_Vrms: 3.5kV
U2 = CMP-0095299-2: 750kHz Wide VIN/VOUT Range LLC Controller Optimized for Light Load Efficiency; Manufacturer: Texas Instruments; Number Of Outputs: 2; TaMax_C: +125°C; Output Type: Other; TJmax_C: +150°C; AEC Qualified: No; Standoff Height: 0.1mm; TaMin_C: -40°C; SizeZ_mm: 1.75mm; Switching Frequency: 30-750kHz; Max Supply Voltage: 18.5V; AEC Category: Q200; CompType: IC
U3 U4 = CMP-0006173-3: Optocoupler, 5 kV, 80-160% CTR, TH; Manufacturer: Fairchild Semiconductor; CTR (Max): 160%; SizeAreaWB_mm2: 71.064; CTR (Min): 80%; SizeZ_mm: 5; SizeX_mm: 8.8; SizeY_mm: 4.58; SizeArea_mm2: 40.304; Voltage_Isolation_Vrms: 5kV
U5 = CMP-0084729-1: Programmable Shunt Regulator with Optimized Reference Current, DBZ0003A (SOT-23-3); Manufacturer: Texas Instruments; SizeY_mm: 3; SizeZ_mm: 1.12; SizeX_mm: 2.5; SizeAreaWB_mm2: 14; CompType: IC; AEC Qualified: N; AEC Category: Q200; SizeArea_mm2: 7.5
U6 = CMP-0075718-1: GENERAL-PURPOSE LOW-VOLTAGE COMPARATORS, D0008A (SOIC-8); Manufacturer: Texas Instruments; SizeAreaWB_mm2: 56.58; SizeArea_mm2: 30.38; SizeZ_mm: 1.75; SizeY_mm: 6.2; U/M: EA; CompType: IC; SizeX_mm: 4.9
U7 = CMP-0043697-1: Dual Operational Amplifier with Internal Reference, 3 to 32 V, -40 to 105 degC, 8-pin SOIC (D8), Green (RoHS & no Sb/Br); Manufacturer: Texas Instruments; Vio (25C)(Max)(mV): 4; GBW(Typ)(MHz): 0.9; CMRR(Min)(dB): 70; Total Supply Voltage(Max)(+5V is 5, +/-5V is 10): 32; Iq per channel(Max)(mA): 0.6; Total Supply Voltage(Min)(+5V is 5, +/-5V is 10): 3; Number of Channels: 2; Vn at 1kHz(Typ)(nV/rtHz): 50; Offset Drift(Typ)(uV/C): 7; Rating: Catalog; IIB(Max)(pA): 150000; Sub Family: General Purpose Amplifier, High Supply Voltage Amplifier (>=30V); Slew Rate(Typ)(V/us): 0.4
U8 = CMP-0013064-2: Low- and High-Side Measurement, Multichannel, Voltage Output, Current-Sense Amplifier, DBV0005A (SOT-5); Manufacturer: Texas Instruments; SizeX_mm: 2.8; SizeY_mm: 2.9; CompType: IC; SizeZ_mm: 1.45; SizeArea_mm2: 8.12; SizeAreaWB_mm2: 14.82; U/M: EA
